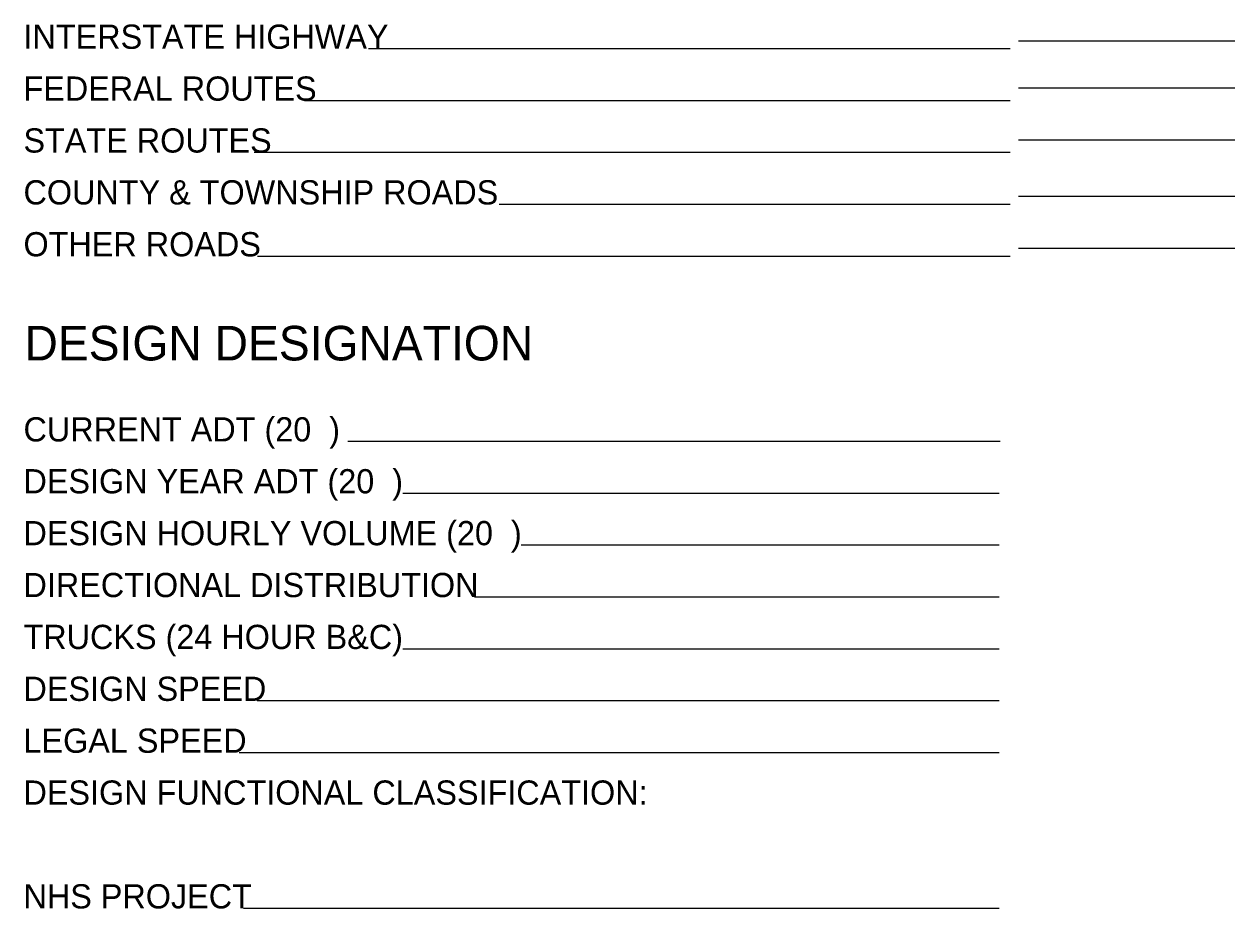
# Model space of a CAD drawing. Extents: x 0 to 69.5, y -4.5 to 22.
# Drawn here: x 39.83 to 46.84, y 2.14 to 7.26 of the extents above; entities that cross this region are included whole.
import ezdxf

# ---------------------------------------------------------------- set-up
doc = ezdxf.new("R2010")
doc.units = 0
doc.layers.add('SH_Data', color=7, linetype='Continuous')
doc.layers.add('SH_Text', color=7, linetype='Continuous')

msp = doc.modelspace()

# ---------------------------------------------------------------- linework, layer by layer
at = {"layer": 'SH_Data'}
for p, q in [((46.8361, 7.1602), (45.5861, 7.1602)), ((45.5361, 7.1161), (41.8256, 7.1161)), ((46.8361, 6.8885), (45.5861, 6.8885)), ((45.5361, 6.8161), (41.4553, 6.8161)), ((46.8361, 6.5885), (45.5861, 6.5885)), ((45.5361, 6.5161), (41.1649, 6.5161)), ((46.8361, 6.2618), (45.5861, 6.2618)), ((45.5361, 6.2161), (42.5813, 6.2161)), ((46.8361, 5.9618), (45.5861, 5.9618)), ((45.5361, 5.9161), (41.1832, 5.9161)), ((45.4785, 4.8457), (41.7071, 4.8457)), ((45.4729, 4.5457), (42.0246, 4.5457)), ((45.4729, 4.2457), (42.7084, 4.2457)), ((45.4729, 3.9457), (42.4398, 3.9457)), ((45.4729, 3.6457), (42.0246, 3.6457)), ((45.4729, 3.3457), (41.1821, 3.3457)), ((45.4729, 3.0457), (41.0783, 3.0457)), ((45.4729, 2.1457), (41.103, 2.1457))]:
    msp.add_line(p, q, dxfattribs=at)

# ---------------------------------------------------------------- texts
msp.add_text('DESIGN DESIGNATION', height=0.2, dxfattribs=at).set_placement((39.8361, 5.3141))
at = {"layer": 'SH_Text'}
for s, p in [('INTERSTATE HIGHWAY', (39.8305, 7.1161)), ('FEDERAL ROUTES', (39.8305, 6.8161)), ('STATE ROUTES', (39.8305, 6.5161)), ('COUNTY & TOWNSHIP ROADS', (39.8305, 6.2161)), ('OTHER ROADS', (39.8305, 5.9161)), ('CURRENT ADT (20  )', (39.8305, 4.8457)), ('DESIGN YEAR ADT (20  )', (39.8305, 4.5457)), ('DESIGN HOURLY VOLUME (20  )', (39.8305, 4.2457)), ('DIRECTIONAL DISTRIBUTION', (39.8305, 3.9457)), ('TRUCKS (24 HOUR B&C)', (39.8305, 3.6457)), ('DESIGN SPEED', (39.8305, 3.3457)), ('LEGAL SPEED', (39.8305, 3.0457)), ('DESIGN FUNCTIONAL CLASSIFICATION:', (39.8305, 2.7457)), ('NHS PROJECT', (39.8305, 2.1457))]:
    msp.add_text(s, height=0.14, dxfattribs=at).set_placement(p)

doc.saveas('drawing.dxf')
